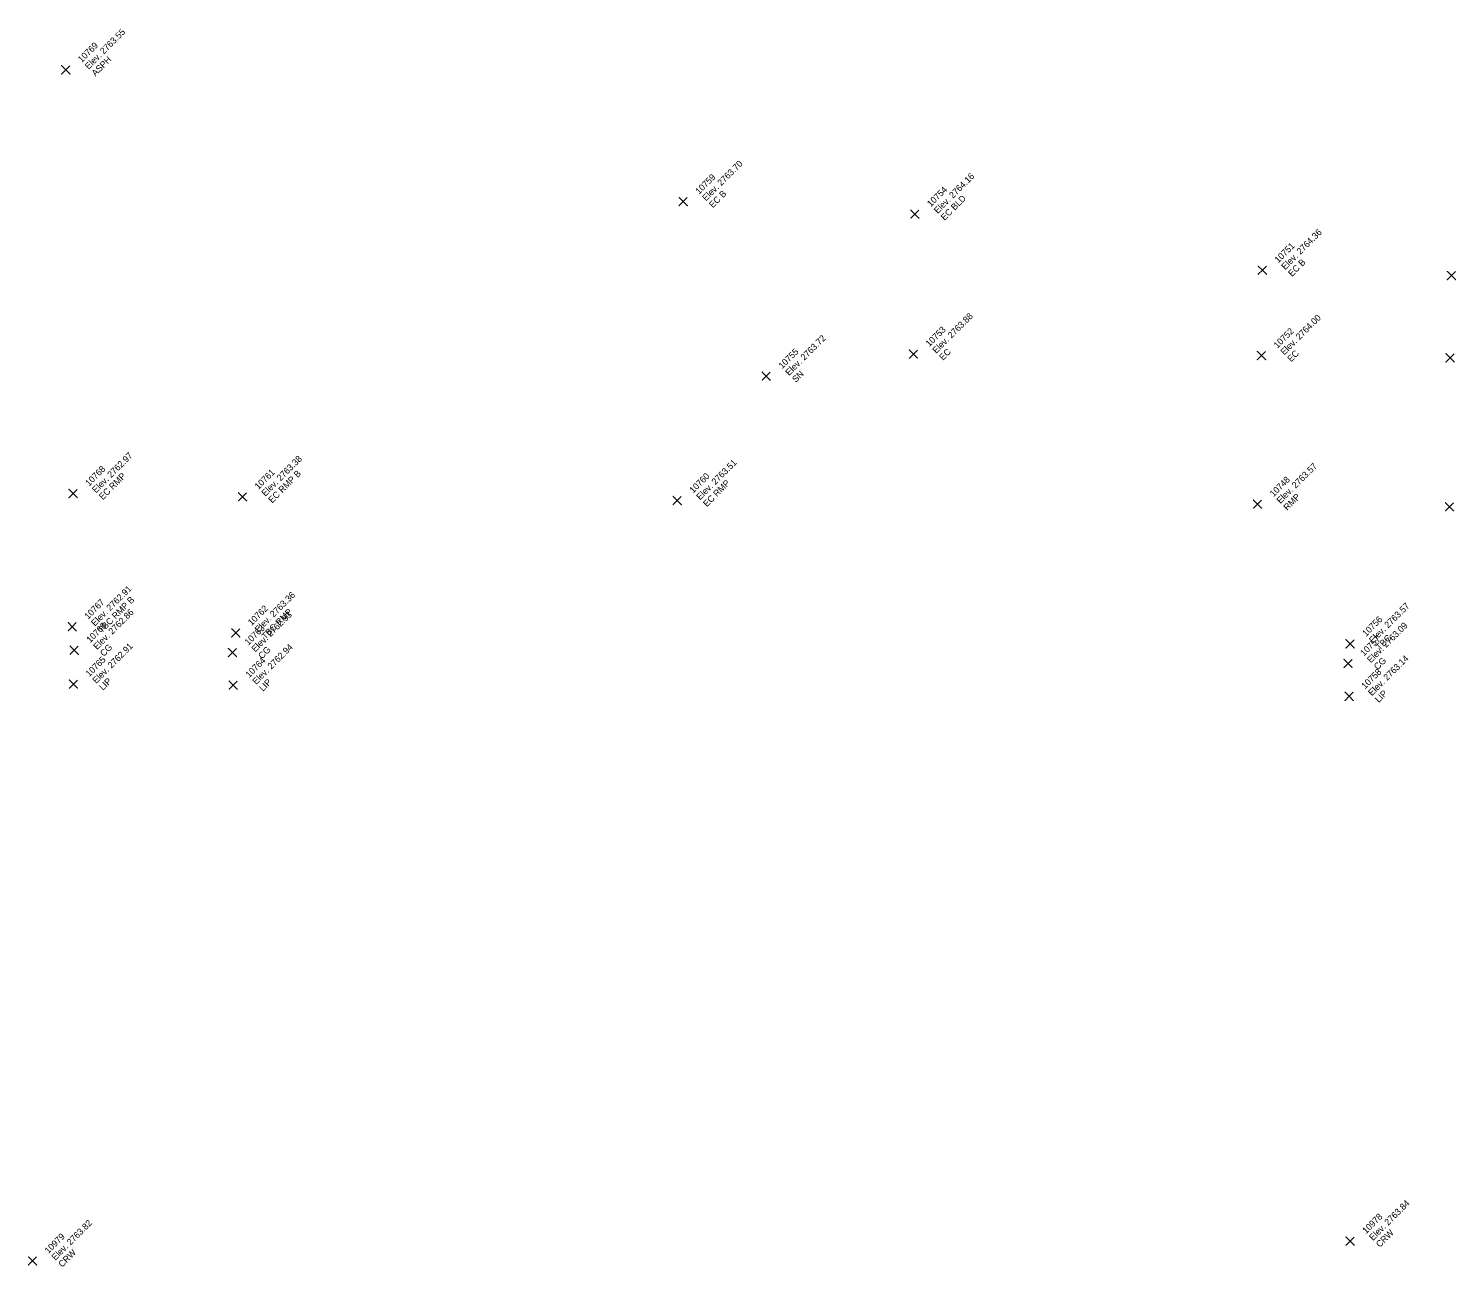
# Model space of a CAD drawing. Extents: x 2493999 to 2503109, y 700767 to 706646.
# Drawn here: x 2502500.4 to 2502553.5, y 701337.8 to 701383.9 of the extents above; entities that cross this region are included whole.
import ezdxf

# ---------------------------------------------------------------- set-up
doc = ezdxf.new("R2010")
doc.units = 0
doc.layers.add('ALG_CL_BLUE_Horiz', color=7, linetype='Continuous')
doc.layers.add('DES_SURFACE_Existing-Ground', color=7, linetype='Continuous')

msp = doc.modelspace()

# ---------------------------------------------------------------- linework, layer by layer
at = {"layer": 'ALG_CL_BLUE_Horiz'}
for points in [[(2502501.75, 701382.332), (2502501.6, 701382.482), (2502501.75, 701382.332), (2502501.6, 701382.182), (2502501.75, 701382.332), (2502501.9, 701382.182), (2502501.75, 701382.332), (2502501.9, 701382.482)], [(2502524.744, 701377.424), (2502524.594, 701377.574), (2502524.744, 701377.424), (2502524.594, 701377.274), (2502524.744, 701377.424), (2502524.894, 701377.274), (2502524.744, 701377.424), (2502524.894, 701377.574)], [(2502533.374, 701376.958), (2502533.224, 701377.108), (2502533.374, 701376.958), (2502533.224, 701376.808), (2502533.374, 701376.958), (2502533.524, 701376.808), (2502533.374, 701376.958), (2502533.524, 701377.108)], [(2502546.314, 701374.868), (2502546.164, 701375.018), (2502546.314, 701374.868), (2502546.164, 701374.718), (2502546.314, 701374.868), (2502546.464, 701374.718), (2502546.314, 701374.868), (2502546.464, 701375.018)], [(2502553.356, 701374.67), (2502553.206, 701374.82), (2502553.356, 701374.67), (2502553.206, 701374.52), (2502553.356, 701374.67), (2502553.506, 701374.52), (2502553.356, 701374.67), (2502553.506, 701374.82)], [(2502533.319, 701371.746), (2502533.169, 701371.896), (2502533.319, 701371.746), (2502533.169, 701371.596), (2502533.319, 701371.746), (2502533.469, 701371.596), (2502533.319, 701371.746), (2502533.469, 701371.896)], [(2502546.282, 701371.688), (2502546.132, 701371.838), (2502546.282, 701371.688), (2502546.132, 701371.538), (2502546.282, 701371.688), (2502546.432, 701371.538), (2502546.282, 701371.688), (2502546.432, 701371.838)], [(2502553.305, 701371.604), (2502553.155, 701371.754), (2502553.305, 701371.604), (2502553.155, 701371.454), (2502553.305, 701371.604), (2502553.455, 701371.454), (2502553.305, 701371.604), (2502553.455, 701371.754)], [(2502527.839, 701370.924), (2502527.689, 701371.074), (2502527.839, 701370.924), (2502527.689, 701370.774), (2502527.839, 701370.924), (2502527.989, 701370.774), (2502527.839, 701370.924), (2502527.989, 701371.074)], [(2502502.021, 701366.551), (2502501.871, 701366.701), (2502502.021, 701366.551), (2502501.871, 701366.401), (2502502.021, 701366.551), (2502502.171, 701366.401), (2502502.021, 701366.551), (2502502.171, 701366.701)], [(2502508.332, 701366.43), (2502508.182, 701366.58), (2502508.332, 701366.43), (2502508.182, 701366.28), (2502508.332, 701366.43), (2502508.482, 701366.28), (2502508.332, 701366.43), (2502508.482, 701366.58)], [(2502524.524, 701366.289), (2502524.374, 701366.439), (2502524.524, 701366.289), (2502524.374, 701366.139), (2502524.524, 701366.289), (2502524.674, 701366.139), (2502524.524, 701366.289), (2502524.674, 701366.439)], [(2502546.138, 701366.156), (2502545.988, 701366.306), (2502546.138, 701366.156), (2502545.988, 701366.006), (2502546.138, 701366.156), (2502546.288, 701366.006), (2502546.138, 701366.156), (2502546.288, 701366.306)], [(2502553.285, 701366.056), (2502553.135, 701366.206), (2502553.285, 701366.056), (2502553.135, 701365.906), (2502553.285, 701366.056), (2502553.435, 701365.906), (2502553.285, 701366.056), (2502553.435, 701366.206)], [(2502501.988, 701361.59), (2502501.838, 701361.74), (2502501.988, 701361.59), (2502501.838, 701361.44), (2502501.988, 701361.59), (2502502.138, 701361.44), (2502501.988, 701361.59), (2502502.138, 701361.74)], [(2502508.078, 701361.356), (2502507.928, 701361.506), (2502508.078, 701361.356), (2502507.928, 701361.206), (2502508.078, 701361.356), (2502508.228, 701361.206), (2502508.078, 701361.356), (2502508.228, 701361.506)], [(2502549.582, 701360.95), (2502549.432, 701361.1), (2502549.582, 701360.95), (2502549.432, 701360.8), (2502549.582, 701360.95), (2502549.732, 701360.8), (2502549.582, 701360.95), (2502549.732, 701361.1)], [(2502502.064, 701360.715), (2502501.914, 701360.865), (2502502.064, 701360.715), (2502501.914, 701360.565), (2502502.064, 701360.715), (2502502.214, 701360.565), (2502502.064, 701360.715), (2502502.214, 701360.865)], [(2502507.957, 701360.626), (2502507.807, 701360.776), (2502507.957, 701360.626), (2502507.807, 701360.476), (2502507.957, 701360.626), (2502508.107, 701360.476), (2502507.957, 701360.626), (2502508.107, 701360.776)], [(2502549.506, 701360.22), (2502549.356, 701360.37), (2502549.506, 701360.22), (2502549.356, 701360.07), (2502549.506, 701360.22), (2502549.656, 701360.07), (2502549.506, 701360.22), (2502549.656, 701360.37)], [(2502502.033, 701359.451), (2502501.883, 701359.601), (2502502.033, 701359.451), (2502501.883, 701359.301), (2502502.033, 701359.451), (2502502.183, 701359.301), (2502502.033, 701359.451), (2502502.183, 701359.601)], [(2502507.988, 701359.416), (2502507.838, 701359.566), (2502507.988, 701359.416), (2502507.838, 701359.266), (2502507.988, 701359.416), (2502508.138, 701359.266), (2502507.988, 701359.416), (2502508.138, 701359.566)], [(2502549.548, 701358.995), (2502549.398, 701359.145), (2502549.548, 701358.995), (2502549.398, 701358.845), (2502549.548, 701358.995), (2502549.698, 701358.845), (2502549.548, 701358.995), (2502549.698, 701359.145)], [(2502549.585, 701338.703), (2502549.435, 701338.853), (2502549.585, 701338.703), (2502549.435, 701338.553), (2502549.585, 701338.703), (2502549.735, 701338.553), (2502549.585, 701338.703), (2502549.735, 701338.853)], [(2502500.512, 701337.963), (2502500.362, 701338.113), (2502500.512, 701337.963), (2502500.362, 701337.813), (2502500.512, 701337.963), (2502500.662, 701337.813), (2502500.512, 701337.963), (2502500.662, 701338.113)]]:
    msp.add_lwpolyline(points, dxfattribs=at)

# ---------------------------------------------------------------- texts
at = {"layer": 'DES_SURFACE_Existing-Ground'}
for s, p in [('10769', (2502502.344, 701382.587)), ('Elev. 2763.55', (2502502.599, 701382.332)), ('ASPH', (2502502.853, 701382.077)), ('Elev. 2763.70', (2502525.593, 701377.424)), ('10759', (2502525.338, 701377.679)), ('Elev. 2764.16', (2502534.223, 701376.958)), ('EC B', (2502525.847, 701377.169)), ('10754', (2502533.968, 701377.213)), ('EC BLD', (2502534.477, 701376.703)), ('Elev. 2764.36', (2502547.163, 701374.868)), ('10751', (2502546.908, 701375.123)), ('EC B', (2502547.417, 701374.613)), ('Elev. 2763.88', (2502534.168, 701371.746)), ('10753', (2502533.913, 701372.001)), ('Elev. 2764.00', (2502547.131, 701371.688)), ('Elev. 2763.72', (2502528.688, 701370.924)), ('10752', (2502546.876, 701371.943)), ('10755', (2502528.433, 701371.179)), ('EC', (2502534.422, 701371.491)), ('EC', (2502547.385, 701371.433)), ('SN', (2502528.942, 701370.669)), ('Elev. 2762.97', (2502502.87, 701366.551)), ('Elev. 2763.38', (2502509.181, 701366.43)), ('10768', (2502502.615, 701366.806)), ('10761', (2502508.926, 701366.685)), ('EC RMP B', (2502509.435, 701366.175)), ('Elev. 2763.51', (2502525.373, 701366.289)), ('Elev. 2763.57', (2502546.987, 701366.156)), ('EC RMP', (2502503.124, 701366.296)), ('10760', (2502525.118, 701366.544)), ('EC RMP', (2502525.627, 701366.034)), ('10748', (2502546.732, 701366.411)), ('RMP', (2502547.241, 701365.901)), ('10767', (2502502.582, 701361.845)), ('Elev. 2762.91', (2502502.837, 701361.59)), ('TBC RMP B', (2502503.091, 701361.335)), ('Elev. 2763.36', (2502508.927, 701361.356)), ('Elev. 2762.86', (2502502.913, 701360.715)), ('10762', (2502508.672, 701361.611)), ('Elev. 2762.93', (2502508.806, 701360.626)), ('TBC RMP', (2502509.181, 701361.101)), ('Elev. 2763.57', (2502550.431, 701360.95)), ('10766', (2502502.658, 701360.97)), ('10763', (2502508.551, 701360.881)), ('10756', (2502550.176, 701361.205)), ('Elev. 2763.09', (2502550.355, 701360.22)), ('10757', (2502550.1, 701360.475)), ('TBC', (2502550.685, 701360.695)), ('Elev. 2762.91', (2502502.882, 701359.451)), ('CG', (2502503.167, 701360.46)), ('Elev. 2762.94', (2502508.837, 701359.416)), ('CG', (2502509.06, 701360.371)), ('Elev. 2763.14', (2502550.397, 701358.995)), ('10765', (2502502.627, 701359.706)), ('10764', (2502508.582, 701359.671)), ('10758', (2502550.142, 701359.25)), ('CG', (2502550.609, 701359.965)), ('LIP', (2502503.136, 701359.196)), ('LIP', (2502509.091, 701359.161)), ('LIP', (2502550.651, 701358.74)), ('Elev. 2763.84', (2502550.434, 701338.703)), ('Elev. 2763.82', (2502501.361, 701337.963)), ('10978', (2502550.179, 701338.958)), ('10979', (2502501.106, 701338.218)), ('CRW', (2502550.688, 701338.448)), ('CRW', (2502501.615, 701337.708))]:
    msp.add_text(s, height=0.24, rotation=45, dxfattribs=at).set_placement(p)

doc.saveas('drawing.dxf')
